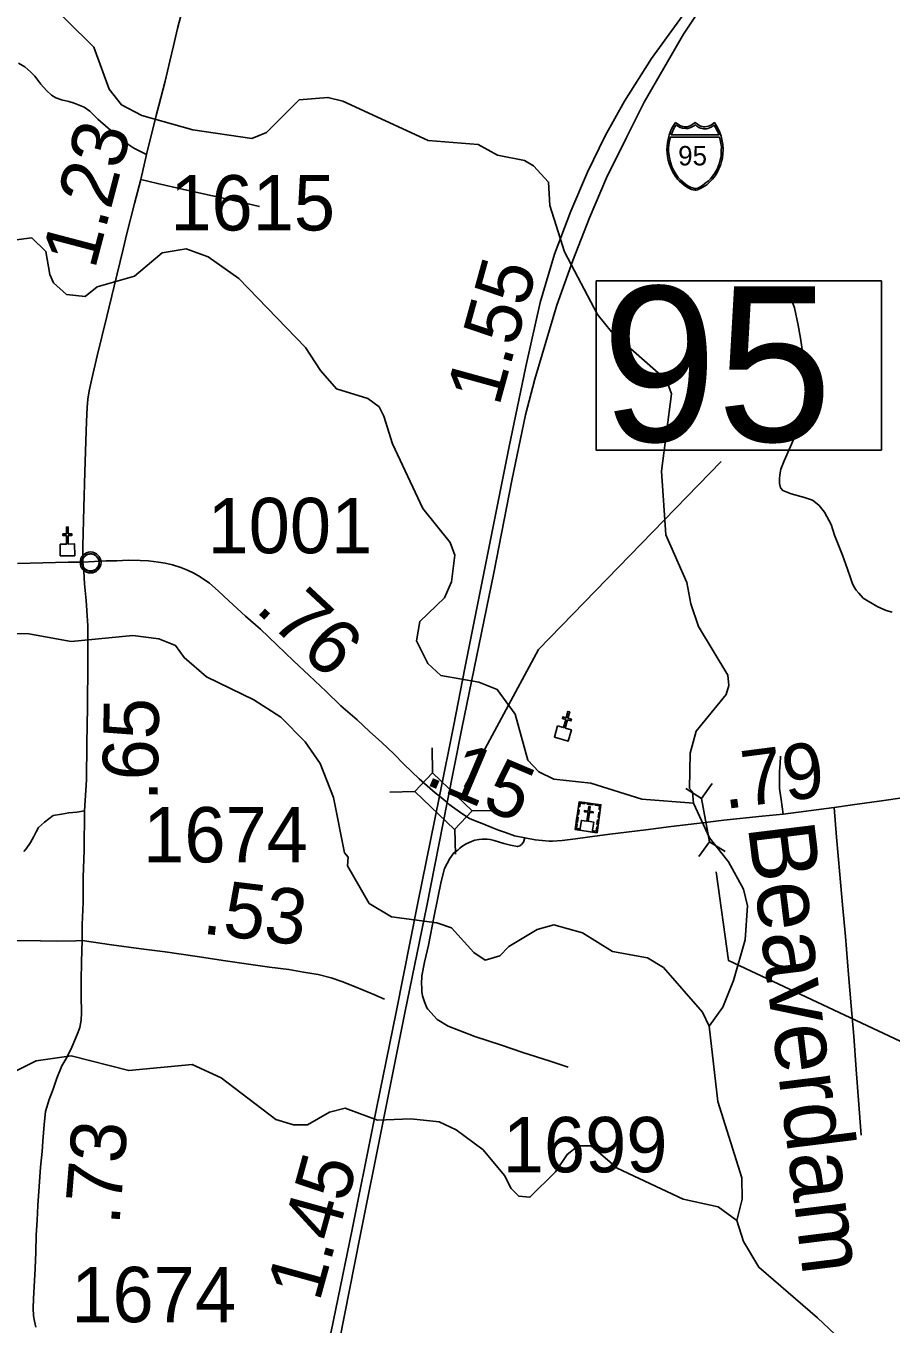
# Model space of a CAD drawing. Extents: x 2290615 to 2522933, y 819489 to 1012715.
# Drawn here: x 2377226 to 2385038, y 930438 to 942161 of the extents above; entities that cross this region are included whole.
import ezdxf

# ---------------------------------------------------------------- set-up
doc = ezdxf.new("R2010")
doc.units = 0
for name, color, linetype in [('Exist Civil Demographics Community CELL', 7, 'Continuous'), ('Exist Cultural Church CELL', 7, 'Continuous'), ('Exist Cultural Church with Cemetery CELL', 7, 'Continuous'), ('Exist Hydrographic Creek Single Shore', 7, 'Continuous'), ('Exist Hydrographic Creek Single Shore Label', 7, 'Continuous'), ('Exist Hydrographic Misc Water Feature', 7, 'Continuous'), ('Exist Road Non-System Type 51', 7, 'Continuous'), ('Exist Road Primary Interstate Divided Center Attributed', 7, 'Continuous'), ('Exist Road Primary Interstate Mileage Hundredths English Label', 7, 'Continuous'), ('Exist Road Primary Interstate Shield CELL', 7, 'Continuous'), ('Exist Road Primary Interstate Shield Number Label', 7, 'Continuous'), ('Exist Road Secondary Mileage Hundredths English Label', 7, 'Continuous'), ('Exist Road Secondary Structure Pipe CELL', 7, 'Continuous'), ('Exist Road Secondary Structure Pipe Number Label', 7, 'Continuous'), ('Exist Road Secondary Structure Standard Bridge CELL', 7, 'Continuous'), ('Exist Road Secondary Structure Standard Bridge Number Label', 7, 'Continuous'), ('Exist Road Secondary Type 10 Attributed', 7, 'Continuous'), ('Exist Road Secondary Type 41 Attributed', 7, 'Continuous'), ('Exist Road Secondary Type 51 Attributed', 7, 'Continuous'), ('Exist Road Secondary Type 51 Number Label', 7, 'Continuous')]:
    doc.layers.add(name, color=color, linetype=linetype)

msp = doc.modelspace()

# ---------------------------------------------------------------- linework, layer by layer
at = {"layer": 'Exist Civil Demographics Community CELL'}
msp.add_lwpolyline([(2377733, 937328), (2377734, 937334), (2377735, 937340), (2377738, 937347), (2377741, 937353), (2377745, 937359), (2377748, 937364), (2377752, 937368), (2377757, 937373), (2377763, 937377), (2377768, 937381), (2377773, 937384), (2377778, 937386), (2377783, 937389), (2377789, 937391), (2377793, 937392), (2377798, 937392), (2377802, 937393), (2377809, 937393), (2377813, 937393), (2377819, 937393), (2377824, 937392), (2377829, 937391), (2377834, 937390), (2377839, 937388), (2377845, 937385), (2377852, 937382), (2377857, 937378), (2377862, 937374), (2377865, 937371), (2377869, 937367), (2377873, 937362), (2377876, 937357), (2377879, 937352), (2377882, 937347), (2377884, 937342), (2377885, 937337), (2377887, 937332), (2377888, 937326), (2377888, 937322), (2377889, 937316), (2377888, 937310), (2377888, 937304), (2377887, 937299), (2377885, 937293), (2377883, 937287), (2377881, 937282), (2377878, 937276), (2377875, 937270), (2377871, 937266), (2377867, 937261), (2377862, 937256), (2377857, 937252), (2377852, 937248), (2377847, 937246), (2377841, 937243), (2377833, 937240), (2377828, 937238), (2377821, 937237), (2377816, 937237), (2377812, 937236), (2377806, 937236), (2377802, 937237), (2377796, 937238), (2377791, 937239), (2377786, 937240), (2377781, 937242), (2377776, 937244), (2377772, 937246), (2377765, 937250), (2377760, 937255), (2377755, 937259), (2377751, 937264), (2377747, 937268), (2377744, 937272), (2377740, 937279), (2377739, 937283), (2377737, 937287), (2377734, 937295), (2377733, 937302), (2377732, 937307), (2377732, 937314), (2377732, 937318), (2377732, 937325)], close=True, dxfattribs=at)
for radius in [94.3, 76.7]:
    msp.add_circle((2377810, 937316), radius, dxfattribs=at)
at = {"layer": 'Exist Cultural Church CELL'}
for points in [[(2377536, 937482), (2377593, 937482), (2377592, 937559), (2377560, 937558), (2377560, 937574), (2377592, 937574), (2377592, 937635), (2377608, 937635), (2377608, 937575), (2377640, 937575), (2377640, 937559), (2377608, 937559), (2377609, 937482), (2377666, 937483), (2377667, 937376), (2377536, 937376)], [(2382026, 935840), (2382081, 935824), (2382101, 935898), (2382070, 935906), (2382075, 935922), (2382105, 935913), (2382121, 935971), (2382137, 935967), (2382121, 935909), (2382152, 935900), (2382147, 935885), (2382117, 935894), (2382096, 935820), (2382152, 935805), (2382123, 935702), (2381998, 935737)]]:
    msp.add_lwpolyline(points, close=True, dxfattribs=at)
at = {"layer": 'Exist Cultural Church with Cemetery CELL'}
for points in [[(2382222, 935155), (2382419, 935127), (2382384, 934875), (2382186, 934903)], [(2382206, 935039), (2382212, 935081), (2382223, 935080), (2382217, 935037)], [(2382216, 935112), (2382227, 935110), (2382232, 935142), (2382272, 935137), (2382273, 935148), (2382222, 935155)], [(2382229, 934897), (2382340, 934881), (2382353, 934971), (2382303, 934978), (2382314, 935058), (2382347, 935054), (2382348, 935065), (2382316, 935069), (2382321, 935111), (2382310, 935113), (2382304, 935071), (2382271, 935076), (2382270, 935065), (2382302, 935060), (2382291, 934979), (2382242, 934986)], [(2382295, 935144), (2382347, 935137), (2382345, 935126), (2382294, 935133)], [(2382413, 935084), (2382402, 935086), (2382406, 935117), (2382366, 935123), (2382368, 935134), (2382419, 935127)], [(2382196, 934972), (2382202, 935015), (2382214, 935013), (2382207, 934970)], [(2382382, 934948), (2382388, 934991), (2382400, 934989), (2382394, 934946)], [(2382392, 935013), (2382398, 935056), (2382409, 935055), (2382403, 935012)], [(2382219, 934898), (2382221, 934910), (2382199, 934913), (2382205, 934953), (2382194, 934954), (2382186, 934903)], [(2382351, 934879), (2382352, 934891), (2382374, 934888), (2382380, 934928), (2382391, 934926), (2382384, 934875)]]:
    msp.add_lwpolyline(points, close=True, dxfattribs=at)
at = {"layer": 'Exist Hydrographic Creek Single Shore'}
for points in [[(2383254, 935142), (2383244, 935243), (2383219, 935275), (2383223, 935593), (2383279, 935793), (2383549, 936122), (2383573, 936205), (2383564, 936297), (2383300, 936736), (2383230, 936943), (2383194, 937135), (2383005, 937564), (2382964, 938140), (2383055, 938840), (2383012, 938963), (2382514, 939399), (2382387, 939554), (2382088, 940120), (2381958, 940541), (2381946, 940751), (2381811, 940899), (2381727, 940945), (2381485, 940994), (2381309, 941092), (2380858, 941126), (2380087, 941482), (2379953, 941516), (2379695, 941495), (2379399, 941198), (2379267, 941146), (2378733, 941223), (2378272, 941352), (2378088, 941449), (2377978, 941589), (2377839, 941971), (2377350, 942456)], [(2383397, 933129), (2383337, 933254), (2382982, 933657), (2382839, 933746), (2382522, 933802), (2382253, 933971), (2381994, 934043), (2381844, 934001), (2381588, 933846), (2381506, 933763), (2381373, 933725), (2381272, 933793), (2381069, 934015), (2380936, 934062), (2380527, 934114), (2380325, 934237), (2380129, 934577), (2380136, 934653), (2380102, 934694), (2380004, 935192), (2379883, 935499), (2379747, 935697), (2379528, 935918), (2379284, 936075), (2378856, 936284), (2378654, 936456), (2378578, 936565), (2378427, 936627), (2378193, 936657), (2377636, 936602), (2377252, 936671), (2376693, 936681)], [(2383397, 933129), (2383520, 933298), (2383617, 933541), (2383720, 933907), (2383741, 934216), (2383706, 934366), (2383569, 934613), (2383400, 934829), (2383254, 935142)], [(2383646, 931373), (2383693, 931565), (2383690, 931759), (2383473, 932446), (2383397, 933129)], [(2383646, 931373), (2383477, 931497), (2383160, 931566), (2382565, 931844), (2382329, 932048), (2382212, 932046), (2382113, 931970), (2382007, 931811), (2381777, 931582), (2381676, 931591), (2381609, 931663), (2381549, 931779), (2381354, 932011), (2381110, 932191), (2380959, 932264), (2380701, 932292), (2380401, 932280), (2380108, 932386), (2379967, 932351), (2379768, 932238), (2379643, 932236), (2379484, 932285), (2378988, 932662), (2378728, 932783), (2378154, 932726), (2377635, 932859), (2377319, 932814), (2377096, 932703)], [(2384892, 929766), (2384649, 929838), (2384481, 929976), (2384488, 930045), (2384594, 930246), (2384585, 930295), (2384374, 930493), (2383843, 930951), (2383707, 931182), (2383646, 931373)]]:
    msp.add_lwpolyline(points, dxfattribs=at)
at = {"layer": 'Exist Hydrographic Misc Water Feature'}
msp.add_lwpolyline([(2383254, 935142), (2382787, 935178), (2382327, 935324), (2381993, 935359), (2381859, 935426), (2381758, 935530), (2381644, 935945), (2381482, 936169), (2381315, 936234), (2380973, 936295), (2380854, 936402), (2380752, 936608), (2380783, 936783), (2381005, 936996), (2381070, 937140), (2381100, 937381), (2381057, 937497), (2380811, 937802), (2380536, 938388), (2380458, 938638), (2380415, 938721), (2380314, 938796), (2380030, 938883), (2379886, 939048), (2379750, 939256), (2379150, 939881), (2378873, 940076), (2378672, 940147), (2378456, 940112), (2378208, 939901), (2377868, 939805), (2377761, 939719), (2377594, 939735), (2377476, 939842), (2377442, 939916), (2377406, 940124), (2377279, 940247), (2376946, 940207)], dxfattribs=at)
at = {"layer": 'Exist Road Non-System Type 51'}
for points in [[(2378316, 940999), (2378201, 941056), (2378155, 941087), (2378058, 941162), (2377970, 941237), (2377874, 941320), (2377802, 941393), (2377753, 941429), (2377661, 941465), (2377614, 941479), (2377546, 941494), (2377496, 941511), (2377456, 941535), (2377413, 941578), (2377360, 941635), (2377306, 941707), (2377267, 941748), (2377216, 941791), (2377160, 941825)], [(2379335, 940532), (2379170, 940569), (2378651, 940684), (2378414, 940739), (2378263, 940776)], [(2385049, 936867), (2384993, 936881), (2384920, 936916), (2384833, 936965), (2384786, 936994), (2384746, 937038), (2384724, 937066), (2384703, 937100), (2384687, 937133), (2384673, 937176), (2384646, 937256), (2384599, 937382), (2384529, 937563), (2384498, 937660), (2384438, 937770), (2384388, 937830), (2384357, 937857), (2384329, 937879), (2384256, 937902), (2384135, 937937), (2384060, 937966), (2384041, 937990), (2384032, 938029), (2384032, 938072), (2384034, 938107), (2384043, 938159), (2384074, 938235), (2384129, 938364), (2384192, 938510), (2384220, 938586), (2384251, 938741), (2384271, 938910), (2384265, 939042), (2384244, 939178), (2384220, 939341), (2384198, 939459), (2384166, 939614), (2384135, 939698)], [(2384041, 935566), (2384037, 935501), (2384032, 935427), (2384030, 935274), (2384046, 935174), (2384065, 935042)], [(2377755, 935074), (2377685, 935062), (2377613, 935056), (2377547, 935043), (2377471, 935029), (2377393, 934969), (2377340, 934921), (2377319, 934883), (2377298, 934842), (2377268, 934787), (2377228, 934728), (2377207, 934705)], [(2384524, 935102), (2384547, 934834), (2384576, 934499), (2384601, 934223), (2384627, 933937), (2384654, 933594), (2384677, 933312), (2384703, 933039), (2384723, 932737), (2384769, 932142)]]:
    msp.add_lwpolyline(points, dxfattribs=at)
at = {"layer": 'Exist Road Primary Interstate Divided Center Attributed'}
for points in [[(2383588, 942862), (2383410, 942607), (2382874, 941866), (2382631, 941483), (2382456, 941170), (2382297, 940841), (2382147, 940490), (2382000, 940099), (2381870, 939665), (2381740, 939086), (2381587, 938347), (2381189, 936361), (2381091, 935849), (2380960, 935204)], [(2381029, 935148), (2381163, 935816), (2381450, 937223), (2381615, 938057), (2381738, 938650), (2381823, 938972), (2382019, 939641), (2382166, 940043), (2382316, 940427), (2382469, 940789), (2382645, 941147), (2382810, 941472), (2383163, 942086), (2383578, 942710), (2383669, 942841)], [(2380960, 935204), (2380762, 934226), (2380570, 933255), (2380361, 932237), (2380172, 931290), (2379957, 930252), (2379728, 929360), (2379513, 928627), (2379370, 928189), (2379215, 927740)], [(2379281, 927667), (2379437, 928113), (2379632, 928662), (2379842, 929365), (2380055, 930273), (2380244, 931235), (2380445, 932239), (2380648, 933247), (2380845, 934215), (2381029, 935148)]]:
    msp.add_lwpolyline(points, dxfattribs=at)
at = {"layer": 'Exist Road Primary Interstate Shield CELL'}
for points in [[(2383268, 940678), (2383278, 940679), (2383291, 940682), (2383303, 940686), (2383317, 940692), (2383338, 940704), (2383355, 940713), (2383374, 940726), (2383400, 940750), (2383426, 940778), (2383449, 940809), (2383468, 940838), (2383484, 940871), (2383497, 940902), (2383508, 940937), (2383515, 940971), (2383518, 941007), (2383521, 941046), (2383518, 941091), (2383510, 941137), (2383503, 941165), (2383492, 941199), (2383483, 941221), (2383462, 941259), (2383443, 941289), (2383416, 941269), (2383398, 941260), (2383388, 941255), (2383376, 941253), (2383356, 941250), (2383343, 941251), (2383331, 941254), (2383321, 941256), (2383313, 941260), (2383268, 941289), (2383224, 941260), (2383215, 941256), (2383205, 941254), (2383196, 941251), (2383181, 941250), (2383170, 941251), (2383158, 941253), (2383148, 941255), (2383138, 941260), (2383093, 941289), (2383075, 941263), (2383060, 941237), (2383045, 941202), (2383036, 941174), (2383029, 941151), (2383020, 941109), (2383016, 941072), (2383015, 941046), (2383020, 940982), (2383027, 940948), (2383034, 940920), (2383058, 940860), (2383076, 940826), (2383092, 940802), (2383113, 940775), (2383125, 940762), (2383170, 940723), (2383200, 940702), (2383223, 940689), (2383235, 940685), (2383252, 940680)], [(2383098, 941268), (2383087, 941251), (2383074, 941228), (2383064, 941204), (2383054, 941178), (2383485, 941178), (2383475, 941201), (2383465, 941223), (2383453, 941244), (2383440, 941264), (2383415, 941248), (2383398, 941240), (2383384, 941235), (2383372, 941232), (2383353, 941231), (2383345, 941231), (2383319, 941237), (2383301, 941244), (2383285, 941256), (2383271, 941268), (2383237, 941248), (2383222, 941241), (2383204, 941236), (2383185, 941234), (2383156, 941237), (2383133, 941245), (2383113, 941256)], [(2383488, 941157), (2383493, 941145), (2383499, 941118), (2383502, 941097), (2383506, 941073), (2383505, 941032), (2383503, 940989), (2383499, 940964), (2383493, 940941), (2383486, 940915), (2383475, 940882), (2383459, 940853), (2383439, 940821), (2383417, 940793), (2383408, 940782), (2383390, 940763), (2383358, 940737), (2383335, 940720), (2383307, 940703), (2383292, 940697), (2383276, 940693), (2383262, 940694), (2383245, 940698), (2383232, 940702), (2383202, 940718), (2383178, 940734), (2383139, 940767), (2383117, 940792), (2383097, 940821), (2383079, 940851), (2383060, 940891), (2383047, 940931), (2383037, 940974), (2383030, 941026), (2383030, 941059), (2383032, 941089), (2383035, 941106), (2383038, 941126), (2383046, 941157)]]:
    msp.add_lwpolyline(points, close=True, dxfattribs=at)
at = {"layer": 'Exist Road Secondary Structure Pipe CELL'}
for p, q in [((2383423, 935319), (2383326, 935184)), ((2383186, 935274), (2383326, 935184)), ((2383400, 934794), (2383326, 935184)), ((2383302, 934659), (2383400, 934794)), ((2383540, 934704), (2383400, 934794))]:
    msp.add_line(p, q, dxfattribs=at)
at = {"layer": 'Exist Road Secondary Structure Pipe Number Label'}
msp.add_lwpolyline([(2383459, 934522), (2383569, 933721), (2385971, 932593)], dxfattribs=at)
at = {"layer": 'Exist Road Secondary Structure Standard Bridge CELL'}
for p, q in [((2380893, 935641), (2380899, 935415)), ((2380512, 935242), (2380739, 935248)), ((2381256, 935072), (2381483, 935077)), ((2381100, 934908), (2381105, 934682))]:
    msp.add_line(p, q, dxfattribs=at)
msp.add_lwpolyline([(2380899, 935415), (2381257, 935073), (2381097, 934905), (2380739, 935248)], close=True, dxfattribs=at)
at = {"layer": 'Exist Road Secondary Structure Standard Bridge Number Label'}
msp.add_lwpolyline([(2382374, 939859), (2384951, 939859), (2384951, 938330), (2382374, 938330)], close=True, dxfattribs=at)
msp.add_lwpolyline([(2381186, 935290), (2381855, 936530), (2383503, 938228)], dxfattribs=at)
at = {"layer": 'Exist Road Secondary Type 10 Attributed'}
msp.add_lwpolyline([(2377734, 933902), (2377677, 933898), (2377514, 933897), (2377359, 933898), (2377093, 933902), (2376841, 933907), (2376645, 933907), (2376125, 933916), (2375705, 933917), (2375380, 933921), (2375318, 933919), (2375293, 933911), (2375266, 933895), (2375248, 933870), (2375173, 933751), (2375120, 933675), (2375079, 933622), (2375055, 933608), (2375034, 933602), (2374979, 933610)], dxfattribs=at)
at = {"layer": 'Exist Road Secondary Type 41 Attributed'}
for points in [[(2381731, 934829), (2381718, 934790), (2381701, 934768), (2381687, 934756), (2381665, 934750), (2381602, 934763), (2381543, 934779), (2381454, 934805), (2381418, 934815), (2381391, 934818), (2381346, 934816), (2381318, 934815), (2381280, 934807), (2381249, 934796), (2381201, 934774), (2381163, 934749), (2381145, 934735), (2381126, 934717), (2381091, 934692), (2381053, 934643), (2381007, 934552), (2380977, 934434), (2380914, 934123), (2380861, 933858), (2380826, 933707), (2380801, 933582), (2380799, 933506), (2380801, 933476), (2380801, 933440), (2380807, 933402), (2380824, 933347), (2380847, 933294), (2380856, 933281)], [(2377734, 933902), (2378000, 933863), (2378266, 933825), (2378484, 933798), (2378771, 933756), (2379029, 933718), (2379237, 933688), (2379425, 933660), (2379600, 933639), (2379733, 933616), (2379864, 933595), (2379981, 933565), (2380078, 933531), (2380194, 933487), (2380279, 933451), (2380367, 933415), (2380465, 933373)], [(2380856, 933281), (2380940, 933189), (2381040, 933127), (2381131, 933093), (2381281, 933034), (2381522, 932956), (2381714, 932890), (2381961, 932812), (2382122, 932759)]]:
    msp.add_lwpolyline(points, dxfattribs=at)
at = {"layer": 'Exist Road Secondary Type 51 Attributed'}
for points in [[(2378626, 942254), (2378596, 942138), (2378560, 941983), (2378526, 941842), (2378484, 941664), (2378427, 941442), (2378402, 941353), (2378316, 940999), (2378263, 940776), (2378206, 940558), (2378138, 940287), (2378105, 940145), (2378024, 939811), (2377958, 939538), (2377869, 939181), (2377820, 938974), (2377797, 938866), (2377786, 938790), (2377779, 938714), (2377773, 938590), (2377767, 938411), (2377757, 938131), (2377749, 937811), (2377740, 937463), (2377740, 937318)], [(2377149, 937306), (2377380, 937313), (2377608, 937318), (2377740, 937318)], [(2377740, 937318), (2377749, 937237), (2377756, 937123), (2377770, 936972), (2377785, 936744), (2377786, 936408), (2377781, 936010), (2377775, 935682), (2377772, 935354), (2377755, 935074), (2377752, 934716), (2377743, 934474), (2377742, 934246), (2377735, 934046), (2377734, 933902)], [(2377740, 937318), (2377950, 937330), (2378048, 937331), (2378149, 937337), (2378257, 937335), (2378333, 937330), (2378424, 937318), (2378484, 937309), (2378549, 937295), (2378625, 937270), (2378686, 937246), (2378743, 937218), (2378799, 937187), (2378884, 937129), (2378961, 937061), (2379058, 936970), (2379209, 936830), (2379343, 936713), (2379491, 936573), (2379641, 936427), (2379783, 936295), (2379937, 936149), (2380070, 936022), (2380216, 935894), (2380328, 935788), (2380441, 935689), (2380547, 935586), (2380638, 935495), (2380712, 935424), (2380778, 935362), (2380850, 935297), (2380921, 935235), (2380960, 935204)], [(2380960, 935204), (2380993, 935177), (2381029, 935148)], [(2383336, 934965), (2383529, 934987), (2383873, 935025), (2384065, 935042), (2384524, 935102), (2384691, 935126), (2384974, 935167), (2385139, 935189), (2385392, 935217), (2385568, 935244), (2385672, 935255), (2385779, 935256), (2385872, 935249)], [(2381029, 935148), (2381046, 935133), (2381098, 935093), (2381163, 935050), (2381233, 935004), (2381299, 934977), (2381345, 934957), (2381433, 934921), (2381493, 934898), (2381557, 934877), (2381638, 934848), (2381731, 934829)], [(2381731, 934829), (2381824, 934811), (2381950, 934799), (2381980, 934798), (2382067, 934804), (2382188, 934821), (2382296, 934834), (2382499, 934861), (2382823, 934901), (2383054, 934932), (2383284, 934959), (2383336, 934965)], [(2377734, 933902), (2377727, 933712), (2377724, 933536), (2377724, 933402), (2377729, 933249), (2377725, 933181), (2377712, 933117), (2377695, 933067), (2377674, 933016), (2377642, 932937), (2377595, 932844), (2377550, 932769), (2377506, 932659), (2377473, 932559), (2377436, 932465), (2377404, 932356), (2377390, 932240), (2377379, 932089), (2377372, 931997), (2377358, 931855), (2377347, 931679), (2377333, 931509), (2377329, 931377), (2377320, 931241), (2377315, 931087), (2377311, 930940), (2377301, 930774), (2377296, 930668), (2377293, 930582), (2377296, 930511), (2377303, 930465), (2377316, 930410)]]:
    msp.add_lwpolyline(points, dxfattribs=at)

# ---------------------------------------------------------------- texts
at = {"layer": 'Exist Hydrographic Creek Single Shore Label'}
msp.add_text('Beaverdam', height=600, rotation=277.0095, dxfattribs=at).set_placement((2383744, 934937))
at = {"layer": 'Exist Road Primary Interstate Mileage Hundredths English Label'}
for s, p in [('1.55', (2381498, 938716)), ('1.45', (2379876, 930629))]:
    msp.add_text(s, height=500, rotation=74.5738, dxfattribs=at).set_placement(p)
at = {"layer": 'Exist Road Primary Interstate Shield Number Label'}
msp.add_text('95', height=175, dxfattribs=at).set_placement((2383116, 940902))
at = {"layer": 'Exist Road Secondary Mileage Hundredths English Label'}
for s, rotation, p in [('1.23', 75.2236, (2377848, 939954)), ('.76', 317.0152, (2379287, 936884)), ('.65', 89.031, (2378414, 935159)), ('.79', 7.3936, (2383536, 935088)), ('.15', 337.0778, (2380815, 935320)), ('.53', 353.1248, (2378808, 933966)), ('.73', 85.3503, (2378069, 931324))]:
    msp.add_text(s, height=500, rotation=rotation, dxfattribs=at).set_placement(p)
at = {"layer": 'Exist Road Secondary Structure Standard Bridge Number Label'}
msp.add_text('95', height=1400, dxfattribs=at).set_placement((2382424, 938409))
at = {"layer": 'Exist Road Secondary Type 51 Number Label'}
for s, p in [('1615', (2378530, 940314)), ('1001', (2378866, 937399))]:
    msp.add_text(s, height=500, rotation=360, dxfattribs=at).set_placement(p)
for s, p in [('1674', (2378285, 934607)), ('1699', (2381532, 931808)), ('1674', (2377636, 930454))]:
    msp.add_text(s, height=500, dxfattribs=at).set_placement(p)

doc.saveas('drawing.dxf')
